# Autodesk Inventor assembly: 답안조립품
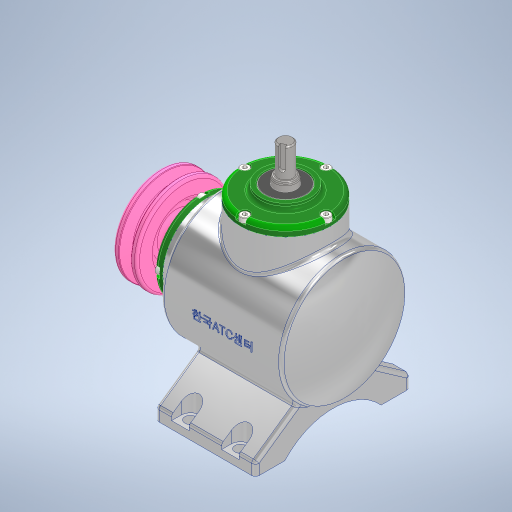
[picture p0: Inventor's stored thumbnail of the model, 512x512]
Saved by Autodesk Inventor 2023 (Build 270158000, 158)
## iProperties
Created: 2023-12
Part Number: 답안조립품
Document SubType Name: Assembly
Designer: asung
Author: asung
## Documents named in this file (17)
- C:\Users\asung\Desktop\731210V1002\답안조립품.iam
- C:\Users\asung\Desktop\731210V1002\본체.ipt
- C:\Users\asung\Desktop\731210V1002\731210V1002\커버.ipt
- C:\Users\asung\Desktop\731210V1002\731210V1002\베어링 6203.ipt
- C:\Users\asung\Desktop\731210V1002\731210V1002\오일실 17 x 32 x 8.ipt
- C:\Users\asung\Desktop\731210V1002\731210V1002\메인 축.ipt
- 메인 축.ipt
- C:\Users\asung\Desktop\731210V1002\731210V1002\키 4 x 4 x 14.ipt
- C:\Users\asung\Desktop\731210V1002\731210V1002\V-벨트풀리.ipt
- C:\Users\asung\Desktop\731210V1002\731210V1002\와셔 4 x 16.ipt
- C:\Users\asung\Desktop\731210V1002\731210V1002\육각볼트 M4 x 8.ipt
- C:\Users\asung\Desktop\731210V1002\731210V1002\서브 축.ipt
- 서브 축.ipt
- C:\Users\asung\Desktop\731210V1002\731210V1002\키 5 x 5 x 14.ipt
- C:\Users\asung\Desktop\731210V1002\731210V1002\메인 베벨기어.ipt
- C:\Users\asung\Desktop\731210V1002\731210V1002\서브 베벨기어.ipt
- C:\Users\asung\Desktop\731210V1002\731210V1002\볼트 M4 x 10.ipt
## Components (1 placed, 1 different names)
1. V-벨트풀리:1
